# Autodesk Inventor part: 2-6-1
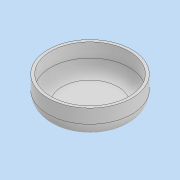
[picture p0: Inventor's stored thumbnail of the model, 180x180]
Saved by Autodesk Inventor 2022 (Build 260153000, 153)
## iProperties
Created: 2021-07
Part Number: 2-6-1
Material: 一般
Document SubType Name: Modeling
Designer: DesignLab
Density: 1 g/cm^3
Appearance: 既定
Author: DesignLab
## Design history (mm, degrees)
sketch "スケッチ1"
  geometry: C1 r 15 at (0, 0); 1 further point
  constraints: 1 centre point, 1 coincident
  dimensions: "d0" = 30 diameter of C1
extrude "押し出し1" new body sketch "スケッチ1" distance "d1" = 10; taper "d2" = 0 deg
fillet "フィレット1" dims "d3" = 5
feature "シェル1" dims "d4" = 1
node "ソリッド1"
